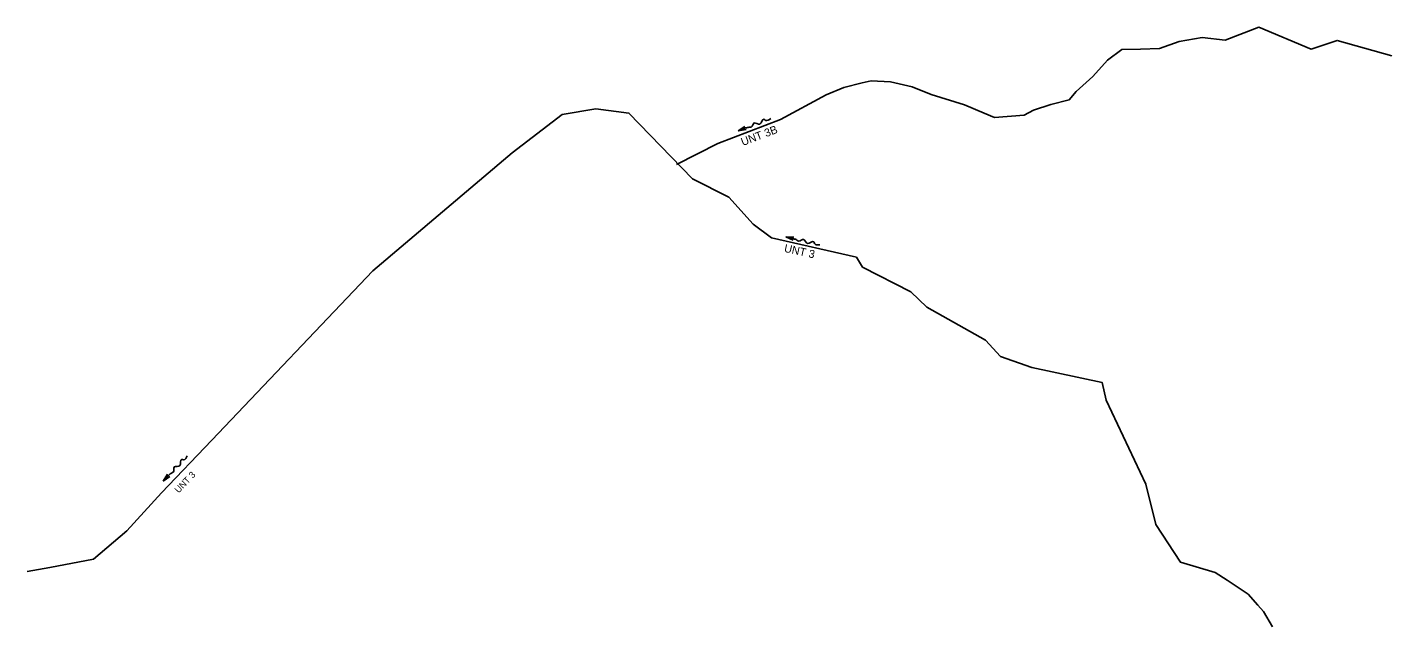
# Model space of a CAD drawing. Extents: x 144323 to 145863, y 512481 to 514373.
# Drawn here: x 145385.8 to 145863.1, y 513233.4 to 513443.2 of the extents above; entities that cross this region are included whole.
import ezdxf

# ---------------------------------------------------------------- set-up
doc = ezdxf.new("R2010")
doc.units = 0
doc.layers.add('HY_X_Text', color=7, linetype='Continuous')
doc.layers.add('HY_X_Water_Edge', color=7, linetype='Continuous')

msp = doc.modelspace()

# ---------------------------------------------------------------- linework, layer by layer
at = {"layer": 'HY_X_Text'}
for p, q in [((145636.83, 513408.46), (145634.41, 513406.93)), ((145634.41, 513406.93), (145637.23, 513407.41)), ((145653.96, 513369.75), (145651.1, 513369.84)), ((145651.1, 513369.84), (145653.7, 513368.66)), ((145434.87, 513286.8), (145433.34, 513284.39)), ((145433.34, 513284.39), (145435.68, 513286.03))]:
    msp.add_line(p, q, dxfattribs=at)
for points in [[(145634.41, 513406.93), (145637.13, 513407.97), (145638.28, 513408.2), (145639.02, 513408.28), (145640.06, 513409.71), (145642.04, 513409.32), (145643.48, 513411.03), (145644.06, 513410.63), (145645.84, 513411.33)], [(145651.1, 513369.84), (145653.93, 513369.18), (145655.01, 513368.73), (145655.68, 513368.38), (145657.34, 513368.98), (145658.75, 513367.54), (145660.9, 513368.15), (145661.16, 513367.49), (145663.03, 513367.07)], [(145433.34, 513284.39), (145435.35, 513286.49), (145436.29, 513287.19), (145436.93, 513287.59), (145437.25, 513289.32), (145439.2, 513289.81), (145439.77, 513291.98), (145440.47, 513291.86), (145441.78, 513293.26)]]:
    msp.add_spline(points, degree=3, dxfattribs=at)
at = {"layer": 'HY_X_Water_Edge'}
for points in [[(145863.07, 513433.23), (145844.03, 513438.62), (145834.9, 513435.6), (145816.54, 513443.21), (145804.82, 513438.65), (145796.74, 513439.59), (145788.74, 513438.24), (145781.79, 513435.77), (145775.2, 513435.55), (145768.67, 513435.42), (145763.7, 513431.73), (145758.49, 513425.95), (145752.73, 513420.77), (145750.3, 513417.84), (145743.88, 513416.15), (145737.78, 513414.14), (145734.53, 513412.4), (145724.18, 513411.68), (145720.55, 513413.11), (145713.58, 513416.1), (145702.01, 513419.72), (145695.29, 513422.34), (145687.72, 513424.15), (145680.99, 513424.43), (145677.86, 513423.76), (145671.45, 513422.16), (145665.25, 513419.52), (145649.33, 513410.88), (145627.41, 513402.58), (145612.85, 513395.17)], [(145821.36, 513233.41), (145818.24, 513238.76), (145816.29, 513240.96), (145812.9, 513244.8), (145805.48, 513249.67), (145801.34, 513252.36), (145789.15, 513255.99), (145780.53, 513269.19), (145777.11, 513283.35), (145763.13, 513312.7), (145761.73, 513318.93), (145737.16, 513324.08), (145726.22, 513328.01), (145720.97, 513333.68), (145700.44, 513345.3), (145694.84, 513350.63), (145677.98, 513359.26), (145675.83, 513362.78), (145646.18, 513369.56), (145639.69, 513374.3), (145631.19, 513383.78), (145618.51, 513390.17), (145596.27, 513413.19), (145584.69, 513414.62), (145572.94, 513412.68), (145555.4, 513399.32), (145506.7, 513357.98), (145450.35, 513298.66), (145432.8, 513280.26), (145420.68, 513267.01), (145408.94, 513257.05), (145393.67, 513254.18), (145385.81, 513252.79)]]:
    msp.add_lwpolyline(points, dxfattribs=at)

# ---------------------------------------------------------------- texts
at = {"layer": 'HY_X_Text'}
for s, height, rotation, p in [('UNT 3B', 2.8, 20.6877, (145636.08, 513401.64)), ('UNT 3', 2.8, 347.4134, (145650.37, 513364.65)), ('UNT 3', 2.29, 46.577, (145438.76, 513280))]:
    msp.add_text(s, height=height, rotation=rotation, dxfattribs=at).set_placement(p)

doc.saveas('drawing.dxf')
